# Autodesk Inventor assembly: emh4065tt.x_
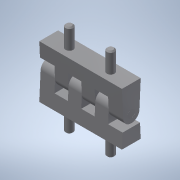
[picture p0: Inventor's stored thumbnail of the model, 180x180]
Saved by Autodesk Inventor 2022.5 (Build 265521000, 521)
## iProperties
Part Number: emh4065tt.x_
Material: 一般
Document SubType Name: Assembly
Designer: ImaoCorp
Sending System: SOLIDWORKS 2017-2017317
MC: AMD64
MC_MODEL: Intel64 Family 6 Model 60 Stepping 3, GenuineIntel
OS: Windows_NT
FRU: Parasolid Version 29.0, build 201,  4-17-2017
FORMAT: text
GUISE: transmit
KEY: emh4065tt
FILE: emh4065tt.x_t
DATE: Mon May 13 14:20:15 2019
Author: ImaoCorp
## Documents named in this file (4)
- X:\14_SW2022-Inv2022\00_全2023-1023新製品(TCC)まで\e\emh4065tt\EMH4065TT.iam
- X:\14_SW2022-Inv2022\00_全2023-1023新製品(TCC)まで\e\emh4065tt\emh4065tt_01.ipt
- X:\14_SW2022-Inv2022\00_全2023-1023新製品(TCC)まで\e\emh4065tt\emh4065tt_02.ipt
- X:\14_SW2022-Inv2022\00_全2023-1023新製品(TCC)まで\e\emh4065tt\emh4065tt_03.ipt
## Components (3 placed, 3 different names)
1. emh4065tt_01
2. emh4065tt_02
3. emh4065tt_03
